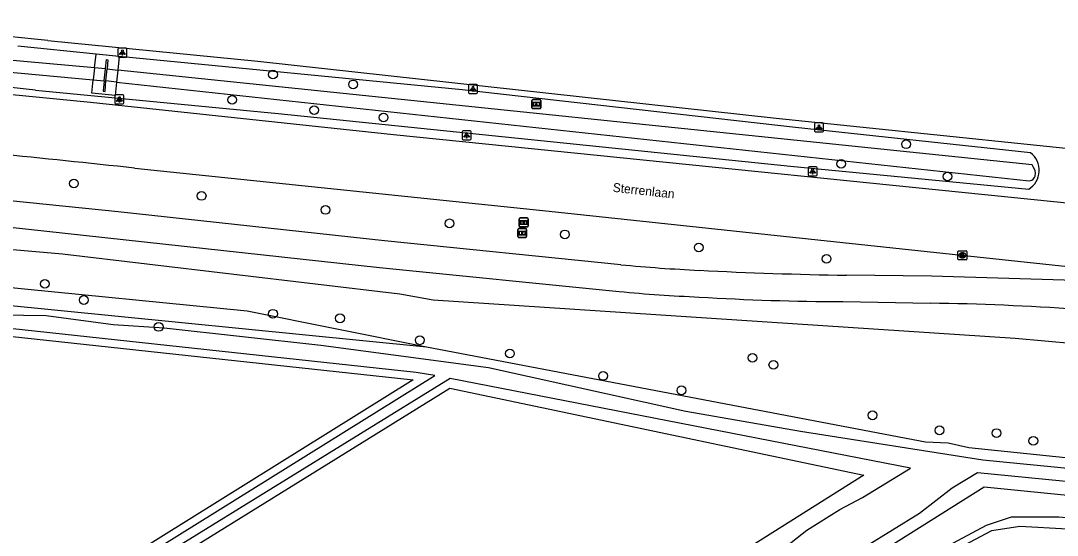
# Model space of a CAD drawing. Extents: x 162791 to 163827, y 385795 to 386523.
# Drawn here: x 163502.6 to 163618.1, y 386456.3 to 386513.6 of the extents above; entities that cross this region are included whole.
import ezdxf

# ---------------------------------------------------------------- set-up
doc = ezdxf.new("R2010")
doc.units = 0
for name, color, linetype in [('IMGEO_Berm_groen', 7, 'Continuous'), ('IMGEO_Boom', 7, 'Continuous'), ('IMGEO_Fietspad_gesloten', 7, 'Continuous'), ('IMGEO_Grasland_overig', 7, 'Continuous'), ('IMGEO_Groenvoorziening', 7, 'Continuous'), ('IMGEO_Informatiebord', 7, 'Continuous'), ('IMGEO_Kolk', 7, 'Continuous'), ('IMGEO_Lichtpunt', 7, 'Continuous'), ('IMGEO_Loofbos', 7, 'Continuous'), ('IMGEO_Muur', 7, 'Continuous'), ('IMGEO_Openbare_ruimte_label', 7, 'Continuous'), ('IMGEO_OVBaan_gesloten', 7, 'Continuous'), ('IMGEO_Rijbaan_regionaal_gesloten', 7, 'Continuous'), ('IMGEO_Terreindeel_open', 7, 'Continuous'), ('IMGEO_Waterloop', 7, 'Continuous')]:
    doc.layers.add(name, color=color, linetype=linetype)

msp = doc.modelspace()

# ---------------------------------------------------------------- linework, layer by layer
at = {"layer": 'IMGEO_Berm_groen'}
for points in [[(163511.02, 386509.9), (163502.27, 386510.77)], [(163513.57, 386509.63), (163511.02, 386509.9)], [(163615.15, 386498.91), (163588.97, 386501.7), (163551.8, 386505.9), (163513.57, 386509.63)], [(163504.26, 386505.87), (163531.29, 386503.26), (163588.4, 386497.4), (163614.95, 386494.84)]]:
    msp.add_lwpolyline(points, dxfattribs=at)
for centre, radius, start, end in [((163382.03, 385355.5), 1156.85, 83.93509, 85.56813), ((163613.66, 386496.94), 2.46, 301.5462, 52.9342)]:
    msp.add_arc(centre, radius, start, end, dxfattribs=at)
at = {"layer": 'IMGEO_Boom'}
for centre in [(163530.72, 386507.63), (163539.65, 386506.52), (163526.18, 386504.8), (163535.31, 386503.65), (163543.05, 386502.83), (163601.28, 386499.85), (163594.05, 386497.66), (163605.9, 386496.26), (163508.54, 386495.48), (163522.77, 386494.09), (163536.58, 386492.53), (163550.4, 386491.03), (163563.26, 386489.8), (163578.17, 386488.34), (163592.42, 386487.08), (163505.29, 386484.29), (163509.64, 386482.49), (163530.72, 386480.96), (163538.19, 386480.45), (163517.98, 386479.49), (163547.08, 386478), (163557.13, 386476.53), (163584.16, 386476.04), (163586.49, 386475.27), (163567.51, 386474.03), (163576.24, 386472.42), (163597.53, 386469.64), (163605, 386467.96), (163611.36, 386467.66), (163615.46, 386466.79)]:
    msp.add_circle(centre, 0.489, dxfattribs=at)
at = {"layer": 'IMGEO_Fietspad_gesloten'}
for points in [[(163569.5, 386486.42), (163543.16, 386489.08), (163513.46, 386492.33), (163497.38, 386493.95), (163476.42, 386495.84), (163451.77, 386497.92), (163447.68, 386498.2)], [(163447.56, 386495.14), (163476.01, 386493.06), (163496.64, 386491.11), (163542.58, 386486.12), (163569.29, 386483.45)], [(163620.13, 386484.65), (163604.12, 386485.16), (163594.65, 386485.25)], [(163594.23, 386482.31), (163603.99, 386482.13)]]:
    msp.add_lwpolyline(points, dxfattribs=at)
for centre, radius, start, end in [((163587.43, 386675.24), 189.67, 264.5734, 267.2209), ((163602.36, 386962.86), 477.67, 267.106, 269.0754), ((163584, 386629.85), 147.14, 264.2612, 267.7498), ((163594.83, 386753.88), 271.57, 266.4926, 269.8717), ((163599.31, 386175.18), 306.99, 86.0704, 89.1257)]:
    msp.add_arc(centre, radius, start, end, dxfattribs=at)
at = {"layer": 'IMGEO_Grasland_overig'}
for points in [[(163452.97, 386432.91), (163452.58, 386432.41), (163452.35, 386431.82), (163452.19, 386431.17), (163460.87, 386414.29), (163463.5, 386412.32), (163466.9, 386409.79), (163468.58, 386408.68), (163494.39, 386391.55), (163496.63, 386391.81), (163497.12, 386391.87), (163498.07, 386392.29), (163499.3, 386392.84), (163500.74, 386394.07), (163502.97, 386394.8), (163508.34, 386398.61), (163530.61, 386411.74), (163609.97, 386461.67), (163649.8, 386457.71), (163652.3, 386455.08)], [(163642, 386454.38), (163641.93, 386455.01), (163641.73, 386455.43), (163641.35, 386455.83), (163640.84, 386456.09), (163640.37, 386456.14), (163639.83, 386456.09), (163636.14, 386455.08), (163632.63, 386455.63), (163622.65, 386457.88), (163618.29, 386458.29), (163612.99, 386458.29), (163610.19, 386457.36), (163600.07, 386451.95), (163589.48, 386445.76), (163508.76, 386394.54), (163502.81, 386390.77), (163501.92, 386389.74), (163500.81, 386388.48), (163530.22, 386368.61), (163554.32, 386352.37), (163689.35, 386265.56)]]:
    msp.add_lwpolyline(points, dxfattribs=at)
at = {"layer": 'IMGEO_Groenvoorziening'}
for points in [[(163416.73, 386495.06), (163447.48, 386493.27), (163467.05, 386491.7), (163487.01, 386489.37), (163500, 386488.25), (163507.28, 386487.62), (163544.86, 386483.18), (163548.58, 386482.52), (163613.44, 386478.23), (163623.37, 386477.33), (163632.55, 386476.27), (163639.45, 386472.52)], [(163547.83, 386477.22), (163527.83, 386481.25), (163500, 386483.98), (163447.12, 386489.17), (163430.63, 386491.16), (163416.94, 386492.4)], [(163547.83, 386477.22), (163500, 386481.98), (163478.33, 386483.02), (163471.73, 386483.62), (163446.86, 386486.47), (163429.92, 386488.14), (163422.42, 386489.1), (163421.6, 386488.64), (163420.9, 386488.1), (163420.52, 386487.53), (163420.36, 386486.51), (163420.49, 386485.85)], [(163653.14, 386461.36), (163608.26, 386466.02), (163605.96, 386466.54), (163603.44, 386466.66), (163547.83, 386477.22)]]:
    msp.add_lwpolyline(points, dxfattribs=at)
at = {"layer": 'IMGEO_Informatiebord'}
for p, q in [((163559.58, 386503.92), (163559.58, 386504.72)), ((163559.58, 386504.72), (163559.58, 386503.92)), ((163559.68, 386504.82), (163560.47, 386504.82)), ((163560.47, 386504.82), (163559.68, 386504.82)), ((163560.57, 386504.72), (163560.57, 386503.92)), ((163560.57, 386503.92), (163560.57, 386504.72)), ((163560.47, 386503.82), (163559.68, 386503.82)), ((163559.68, 386503.82), (163560.47, 386503.82)), ((163558.16, 386490.73), (163558.16, 386491.53)), ((163558.16, 386491.53), (163558.16, 386490.73)), ((163558.26, 386491.63), (163559.05, 386491.63)), ((163559.05, 386491.63), (163558.26, 386491.63)), ((163559.05, 386490.63), (163558.26, 386490.63)), ((163558.26, 386490.63), (163559.05, 386490.63)), ((163559.15, 386491.53), (163559.15, 386490.73)), ((163559.15, 386490.73), (163559.15, 386491.53)), ((163558, 386489.55), (163558, 386490.35)), ((163558, 386490.35), (163558, 386489.55)), ((163558.1, 386490.45), (163558.89, 386490.45)), ((163558.89, 386490.45), (163558.1, 386490.45)), ((163558.89, 386489.45), (163558.1, 386489.45)), ((163558.1, 386489.45), (163558.89, 386489.45)), ((163558.99, 386490.35), (163558.99, 386489.55)), ((163558.99, 386489.55), (163558.99, 386490.35))]:
    msp.add_line(p, q, dxfattribs=at)
for points in [[(163559.68, 386504.55), (163560.47, 386504.55), (163560.47, 386504.09), (163559.68, 386504.09), (163559.68, 386504.55)], [(163559.75, 386504.49), (163559.75, 386504.15), (163560.02, 386504.15), (163560.02, 386504.37), (163560.13, 386504.37), (163560.13, 386504.15), (163560.41, 386504.15), (163560.41, 386504.49), (163560.13, 386504.49), (163560.13, 386504.41), (163560.02, 386504.41), (163560.02, 386504.49), (163559.75, 386504.49)], [(163558.26, 386491.36), (163559.05, 386491.36), (163559.05, 386490.89), (163558.26, 386490.89), (163558.26, 386491.36)], [(163558.33, 386491.29), (163558.33, 386490.96), (163558.6, 386490.96), (163558.6, 386491.17), (163558.71, 386491.17), (163558.71, 386490.96), (163558.99, 386490.96), (163558.99, 386491.29), (163558.71, 386491.29), (163558.71, 386491.21), (163558.6, 386491.21), (163558.61, 386491.29), (163558.33, 386491.29)], [(163558.1, 386490.18), (163558.89, 386490.18), (163558.89, 386489.72), (163558.1, 386489.72), (163558.1, 386490.18)], [(163558.16, 386490.12), (163558.16, 386489.78), (163558.44, 386489.78), (163558.44, 386489.99), (163558.54, 386489.99), (163558.54, 386489.78), (163558.82, 386489.78), (163558.82, 386490.12), (163558.55, 386490.12), (163558.55, 386490.03), (163558.44, 386490.03), (163558.44, 386490.12), (163558.16, 386490.12)]]:
    msp.add_lwpolyline(points, dxfattribs=at)
for centre, start, end in [((163559.68, 386504.72), 90, 180), ((163559.68, 386504.72), 90, 180), ((163560.47, 386504.72), 0, 90), ((163560.47, 386504.72), 360, 90), ((163559.68, 386503.92), 180, 270), ((163559.68, 386503.92), 180, 270), ((163560.47, 386503.92), 270, 0), ((163560.47, 386503.92), 270, 0), ((163558.26, 386491.53), 90, 180), ((163558.26, 386491.53), 90, 180), ((163558.26, 386490.73), 180, 270), ((163558.26, 386490.73), 180, 270), ((163559.05, 386491.53), 0, 90), ((163559.05, 386491.53), 360, 90), ((163559.05, 386490.73), 270, 0), ((163559.05, 386490.73), 270, 0), ((163558.1, 386490.35), 90, 180), ((163558.1, 386490.35), 90, 180), ((163558.1, 386489.55), 180, 270), ((163558.1, 386489.55), 180, 270), ((163558.89, 386490.35), 0, 90), ((163558.89, 386490.35), 360, 90), ((163558.89, 386489.55), 270, 0), ((163558.89, 386489.55), 270, 0)]:
    msp.add_arc(centre, 0.1, start, end, dxfattribs=at)
at = {"layer": 'IMGEO_Kolk'}
for p, q in [((163607.06, 386487.04), (163607.06, 386487.9)), ((163607.13, 386487.97), (163607.99, 386487.97)), ((163607.57, 386487.19), (163607.54, 386487.19)), ((163607.55, 386487.75), (163607.57, 386487.75)), ((163608.06, 386487.9), (163608.06, 386487.04)), ((163607.99, 386486.97), (163607.13, 386486.97))]:
    msp.add_line(p, q, dxfattribs=at)
for points in [[(163607.06, 386487.04), (163607.06, 386487.9)], [(163607.13, 386487.97), (163607.99, 386487.97)], [(163607.38, 386487.67), (163607.5, 386487.67), (163607.5, 386487.52), (163607.63, 386487.67), (163607.8, 386487.67), (163607.65, 386487.52), (163607.8, 386487.27), (163607.65, 386487.27), (163607.57, 386487.43), (163607.5, 386487.37), (163607.5, 386487.27), (163607.38, 386487.27), (163607.38, 386487.67)], [(163608.06, 386487.9), (163608.06, 386487.04)], [(163607.99, 386486.97), (163607.13, 386486.97)]]:
    msp.add_lwpolyline(points, dxfattribs=at)
for centre, start, end in [((163607.13, 386487.89), 91.552, 178.448), ((163607.13, 386487.89), 91.552, 178.448), ((163607.98, 386487.89), 1.552, 88.448), ((163607.98, 386487.89), 1.552, 88.448), ((163607.13, 386487.04), 181.552, 268.448), ((163607.13, 386487.04), 181.552, 268.448), ((163607.98, 386487.04), 271.552, 358.448), ((163607.98, 386487.04), 271.552, 358.448)]:
    msp.add_arc(centre, 0.0765, start, end, dxfattribs=at)
for centre, major_axis, ratio, start_param, end_param in [((163607.55, 386487.47), (-0.387, 0.002), 0.722429, 4.712389, 7.853982), ((163607.57, 386487.47), (-0.39, 0.002), 0.717154, 1.570796, 4.712389)]:
    msp.add_ellipse(centre, major_axis=major_axis, ratio=ratio, start_param=start_param, end_param=end_param, dxfattribs=at)
at = {"layer": 'IMGEO_Lichtpunt'}
for p, q in [((163513.44, 386510.46), (163513.44, 386509.66)), ((163513.44, 386510.46), (163513.44, 386509.66)), ((163514.35, 386510.56), (163513.54, 386510.56)), ((163514.35, 386510.56), (163513.54, 386510.56)), ((163514.44, 386509.66), (163514.44, 386510.46)), ((163514.44, 386509.66), (163514.44, 386510.46)), ((163513.54, 386509.56), (163514.35, 386509.56)), ((163513.54, 386509.56), (163514.35, 386509.56)), ((163552.51, 386506.42), (163552.51, 386505.61)), ((163552.51, 386506.42), (163552.51, 386505.61)), ((163553.41, 386506.52), (163552.6, 386506.52)), ((163553.41, 386506.52), (163552.6, 386506.52)), ((163553.5, 386505.61), (163553.5, 386506.42)), ((163553.5, 386505.61), (163553.5, 386506.42)), ((163513.11, 386505.25), (163513.11, 386504.45)), ((163513.11, 386505.25), (163513.11, 386504.45)), ((163514.01, 386505.35), (163513.21, 386505.35)), ((163514.01, 386505.35), (163513.21, 386505.35)), ((163514.11, 386504.45), (163514.11, 386505.25)), ((163514.11, 386504.45), (163514.11, 386505.25)), ((163552.6, 386505.52), (163553.41, 386505.52)), ((163552.6, 386505.52), (163553.41, 386505.52)), ((163513.21, 386504.35), (163514.01, 386504.35)), ((163513.21, 386504.35), (163514.01, 386504.35)), ((163591.07, 386502.13), (163591.07, 386501.32)), ((163591.07, 386502.13), (163591.07, 386501.32)), ((163591.97, 386502.23), (163591.16, 386502.23)), ((163591.97, 386502.23), (163591.16, 386502.23)), ((163592.06, 386501.32), (163592.06, 386502.13)), ((163592.06, 386501.32), (163592.06, 386502.13)), ((163551.8, 386501.25), (163551.8, 386500.44)), ((163551.8, 386501.25), (163551.8, 386500.44)), ((163552.71, 386501.34), (163551.9, 386501.34)), ((163552.71, 386501.34), (163551.9, 386501.34)), ((163552.8, 386500.44), (163552.8, 386501.25)), ((163552.8, 386500.44), (163552.8, 386501.25)), ((163591.16, 386501.23), (163591.97, 386501.23)), ((163591.16, 386501.23), (163591.97, 386501.23)), ((163551.9, 386500.35), (163552.71, 386500.35)), ((163551.9, 386500.35), (163552.71, 386500.35)), ((163590.36, 386497.23), (163590.36, 386496.43)), ((163590.36, 386497.23), (163590.36, 386496.43)), ((163591.27, 386497.33), (163590.46, 386497.33)), ((163591.27, 386497.33), (163590.46, 386497.33)), ((163590.46, 386496.33), (163591.27, 386496.33)), ((163590.46, 386496.33), (163591.27, 386496.33)), ((163591.36, 386496.43), (163591.36, 386497.23)), ((163591.36, 386496.43), (163591.36, 386497.23))]:
    msp.add_line(p, q, dxfattribs=at)
for points in [[(163513.82, 386510.13), (163513.86, 386510.1), (163513.67, 386509.84), (163513.63, 386509.86), (163513.82, 386510.13)], [(163513.92, 386510.08), (163513.97, 386510.08), (163513.97, 386509.76), (163513.92, 386509.76), (163513.92, 386510.08)], [(163514.03, 386510.1), (163514.07, 386510.13), (163514.26, 386509.86), (163514.22, 386509.84), (163514.03, 386510.1)], [(163552.88, 386506.08), (163552.92, 386506.06), (163552.73, 386505.79), (163552.69, 386505.82), (163552.88, 386506.08)], [(163552.98, 386506.04), (163553.03, 386506.04), (163553.03, 386505.71), (163552.98, 386505.71), (163552.98, 386506.04)], [(163553.09, 386506.06), (163553.13, 386506.08), (163553.32, 386505.82), (163553.28, 386505.79), (163553.09, 386506.06)], [(163513.49, 386504.92), (163513.53, 386504.89), (163513.34, 386504.63), (163513.3, 386504.66), (163513.49, 386504.92)], [(163513.59, 386504.87), (163513.64, 386504.87), (163513.64, 386504.55), (163513.59, 386504.55), (163513.59, 386504.87)], [(163513.7, 386504.89), (163513.74, 386504.92), (163513.92, 386504.65), (163513.89, 386504.63), (163513.7, 386504.89)], [(163591.44, 386501.79), (163591.48, 386501.77), (163591.29, 386501.5), (163591.25, 386501.53), (163591.44, 386501.79)], [(163591.54, 386501.75), (163591.59, 386501.75), (163591.59, 386501.42), (163591.54, 386501.42), (163591.54, 386501.75)], [(163591.65, 386501.77), (163591.69, 386501.79), (163591.88, 386501.53), (163591.84, 386501.5), (163591.65, 386501.77)], [(163552.18, 386500.91), (163552.22, 386500.89), (163552.03, 386500.62), (163551.99, 386500.65), (163552.18, 386500.91)], [(163552.28, 386500.87), (163552.33, 386500.87), (163552.33, 386500.54), (163552.28, 386500.54), (163552.28, 386500.87)], [(163552.39, 386500.89), (163552.43, 386500.91), (163552.62, 386500.65), (163552.58, 386500.62), (163552.39, 386500.89)], [(163590.74, 386496.9), (163590.78, 386496.87), (163590.59, 386496.61), (163590.55, 386496.64), (163590.74, 386496.9)], [(163590.84, 386496.85), (163590.89, 386496.85), (163590.89, 386496.53), (163590.84, 386496.53), (163590.84, 386496.85)], [(163590.95, 386496.87), (163590.99, 386496.9), (163591.17, 386496.63), (163591.14, 386496.61), (163590.95, 386496.87)]]:
    msp.add_lwpolyline(points, dxfattribs=at)
for centre in [(163513.94, 386510.26), (163553.01, 386506.22), (163513.61, 386505.05), (163552.3, 386501.05), (163591.57, 386501.93), (163590.86, 386497.03)]:
    msp.add_circle(centre, 0.0994, dxfattribs=at)
for centre, start, end in [((163513.54, 386510.46), 90, 180), ((163513.54, 386510.46), 90, 180), ((163514.35, 386510.46), 0, 90), ((163514.35, 386510.46), 0, 90), ((163513.54, 386509.66), 180, 270), ((163513.54, 386509.66), 180, 270), ((163514.35, 386509.66), 270, 0), ((163514.35, 386509.66), 270, 360), ((163552.6, 386506.42), 90, 180), ((163552.6, 386506.42), 90, 180), ((163552.6, 386505.61), 180, 270), ((163552.6, 386505.61), 180, 270), ((163553.41, 386506.42), 0, 90), ((163553.41, 386506.42), 0, 90), ((163553.41, 386505.61), 270, 0), ((163553.41, 386505.61), 270, 360), ((163513.21, 386505.25), 90, 180), ((163513.21, 386505.25), 90, 180), ((163513.21, 386504.45), 180, 270), ((163513.21, 386504.45), 180, 270), ((163514.01, 386505.25), 0, 90), ((163514.01, 386505.25), 0, 90), ((163514.01, 386504.45), 270, 0), ((163514.01, 386504.45), 270, 360), ((163591.16, 386502.13), 90, 180), ((163591.16, 386502.13), 90, 180), ((163591.97, 386502.13), 0, 90), ((163591.97, 386502.13), 0, 90), ((163551.9, 386501.25), 90, 180), ((163551.9, 386501.25), 90, 180), ((163552.71, 386501.25), 0, 90), ((163552.71, 386501.25), 0, 90), ((163591.16, 386501.32), 180, 270), ((163591.16, 386501.32), 180, 270), ((163591.97, 386501.32), 270, 0), ((163591.97, 386501.32), 270, 360), ((163551.9, 386500.44), 180, 270), ((163551.9, 386500.44), 180, 270), ((163552.71, 386500.44), 270, 0), ((163552.71, 386500.44), 270, 360), ((163590.46, 386497.23), 90, 180), ((163590.46, 386497.23), 90, 180), ((163590.46, 386496.43), 180, 270), ((163590.46, 386496.43), 180, 270), ((163591.27, 386497.23), 0, 90), ((163591.27, 386497.23), 0, 90), ((163591.27, 386496.43), 270, 0), ((163591.27, 386496.43), 270, 360)]:
    msp.add_arc(centre, 0.0946, start, end, dxfattribs=at)
at = {"layer": 'IMGEO_Loofbos'}
for points in [[(163426.74, 386484.12), (163427.71, 386484.1), (163429.61, 386483.87), (163459.33, 386482.06), (163470.85, 386479.85), (163499.94, 386478.6), (163546.34, 386473.58), (163499.55, 386444.44), (163499.21, 386444.01), (163499.01, 386443.53), (163499.06, 386443.12)], [(163499.06, 386443.12), (163499.07, 386443.03), (163499.33, 386442.54), (163499.67, 386442.24), (163500.21, 386442.07), (163501.29, 386442.2), (163550.42, 386472.66), (163596.56, 386462.98), (163545.44, 386430.75), (163496.17, 386397.55), (163494.96, 386396.92), (163493.76, 386397.39), (163465.16, 386415.79), (163462.29, 386420.22)]]:
    msp.add_lwpolyline(points, dxfattribs=at)
at = {"layer": 'IMGEO_Muur'}
for points in [[(163512.05, 386508.27), (163512.16, 386509.29), (163512.32, 386509.26), (163512.23, 386508.24)], [(163511.91, 386506.92), (163512.05, 386508.27)], [(163512.11, 386506.9), (163512.23, 386508.24)], [(163511.91, 386506.92), (163511.79, 386505.78), (163512.01, 386505.73), (163512.11, 386506.9)]]:
    msp.add_lwpolyline(points, dxfattribs=at)
at = {"layer": 'IMGEO_OVBaan_gesloten'}
for points in [[(163632.75, 386491.92), (163544.17, 386500.89), (163510.4, 386504.49), (163488.35, 386506.67)], [(163515.31, 386497.18), (163561.49, 386492.38), (163620.33, 386486.11)]]:
    msp.add_lwpolyline(points, dxfattribs=at)
msp.add_arc((163336.57, 384853.39), 1653.48, 83.79437, 84.86628, dxfattribs=at)
at = {"layer": 'IMGEO_Rijbaan_regionaal_gesloten'}
msp.add_lwpolyline([(163505.62, 386511.42), (163529.05, 386509.1), (163586.79, 386502.74), (163633.43, 386497.93)], dxfattribs=at)
msp.add_arc((163376.77, 385264.44), 1253.62, 84.10031, 85.17638, dxfattribs=at)
at = {"layer": 'IMGEO_Terreindeel_open'}
for points in [[(163510.85, 386508.38), (163511.02, 386509.9)], [(163513.57, 386509.63), (163513.42, 386508.12)], [(163512.05, 386508.27), (163510.85, 386508.38)], [(163512.23, 386508.24), (163513.42, 386508.12)], [(163513.29, 386506.77), (163513.15, 386505.28), (163510.54, 386505.54), (163510.7, 386507.03)], [(163510.7, 386507.03), (163511.91, 386506.92)], [(163513.29, 386506.77), (163512.11, 386506.9)]]:
    msp.add_lwpolyline(points, dxfattribs=at)
at = {"layer": 'IMGEO_Waterloop'}
for points in [[(163510.85, 386508.38), (163471.82, 386511.87)], [(163471.7, 386510.65), (163510.7, 386507.03)], [(163510.85, 386508.38), (163510.7, 386507.03)], [(163513.42, 386508.12), (163513.29, 386506.77)], [(163513.29, 386506.77), (163615, 386495.78), (163615.29, 386495.85), (163615.44, 386495.96), (163615.6, 386496.16), (163615.65, 386496.3), (163615.7, 386496.65), (163615.67, 386496.9), (163615.6, 386497.09), (163615.46, 386497.34), (163615.32, 386497.54), (163513.42, 386508.12)], [(163500.41, 386480.85), (163505.44, 386480.75), (163512.93, 386479.75), (163518.59, 386479.4), (163536.04, 386477.46), (163554.73, 386474.95), (163576.74, 386470.11), (163589.51, 386467.87), (163609.83, 386464.66), (163632.16, 386462.47), (163651.47, 386460.58), (163652.32, 386460.47), (163652.71, 386460.42), (163658.13, 386453.01), (163658.52, 386452.48), (163661.01, 386450.8), (163665.08, 386448.08), (163687.09, 386422.34), (163702.95, 386402.58), (163706.89, 386398.7)], [(163500, 386443.71), (163548.76, 386474.08), (163546.68, 386474.41), (163500, 386479.45)], [(163501.52, 386399.22), (163504.19, 386400.84), (163515.05, 386408.19), (163531.75, 386418.91), (163535.71, 386421.83), (163543.97, 386426.98), (163551.79, 386432.18), (163556.04, 386434.7), (163569.58, 386443.61), (163583.42, 386451.96), (163587.42, 386454.65), (163590.22, 386456.83), (163593.88, 386459.15), (163596.44, 386460.49), (163601.76, 386463.74), (163550.47, 386473.73), (163500.49, 386442.92)], [(163650.92, 386459.15), (163609.25, 386463.24), (163606.42, 386461.52), (163602.77, 386458.71), (163593.76, 386453.11), (163589.18, 386450.05), (163586.32, 386448.46), (163583.04, 386446.12), (163576.96, 386442.46), (163565.9, 386436.25), (163564.94, 386435.41), (163558.4, 386430.86), (163556.66, 386429.9), (163553.1, 386427.52), (163551.74, 386426.86), (163548.6, 386424.56), (163542.14, 386420.81), (163530.79, 386413.82), (163524.99, 386410.62), (163517.95, 386406.11), (163512.33, 386402.77), (163508.95, 386400.49), (163504.02, 386397.6), (163502.35, 386396.62)], [(163502.38, 386389.5), (163502.77, 386389.78), (163503.07, 386389.93), (163562.95, 386428.16), (163591.76, 386446.29), (163599.19, 386450.65), (163610.83, 386456.79), (163613.94, 386457.29), (163619.25, 386456.99)]]:
    msp.add_lwpolyline(points, dxfattribs=at)

# ---------------------------------------------------------------- texts
at = {"layer": 'IMGEO_Openbare_ruimte_label'}
msp.add_text('Sterrenlaan', height=1, rotation=353.6851, dxfattribs=at).set_placement((163568.55, 386494.56))

doc.saveas('drawing.dxf')
